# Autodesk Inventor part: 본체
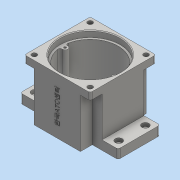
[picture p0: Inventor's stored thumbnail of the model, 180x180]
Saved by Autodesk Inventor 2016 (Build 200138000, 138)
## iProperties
Created: 2020-08
Part Number: 본체
Material: 일반
Document SubType Name: Modeling
Designer: User
Density: 1 g/cm^3
Appearance: 기본값
Mass: 324.574 g
Surface Area: 793.93 cm^2
Volume: 324.574 cm^3
Author: User
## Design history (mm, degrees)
sketch "스케치6"
  geometry: L1 (-70, 30)-(70, 30); L2 (70, 30)-(70, -30); L3 (70, -30)-(-70, -30); L4 (-70, -30)-(-70, 30); L5 (-70, 30)-(70, -30); L6 (70, 30)-(-70, -30); L7 (-33, 47)-(33, 47); L8 (33, 47)-(33, -47); L9 (33, -47)-(-33, -47); L10 (-33, -47)-(-33, 47); L11 (-33, 47)-(33, -47); L12 (33, 47)-(-33, -47); 1 further point
  constraints: 24 end point, 4 midpoint, 4 parallel, 2 horizontal, 2 perpendicular
  dimensions: "d14" = 140 distance of L2.end L3.end; "d15" = 60 distance of L1.end L2.end; "d16" = 66 distance of L8.end L9.end; "d17" = 94 distance of L7.end L8.end
extrude "돌출4" new body sketch "스케치6" distance "d18" = 13; taper "d19" = 0 deg
sketch "스케치8"
  geometry: L1 (-47, 47)-(47, 47); L2 (47, 47)-(47, -47); L3 (47, -47)-(-47, -47); L4 (-47, -47)-(-47, 47); L5 (-47, 47)-(47, -47); L6 (47, 47)-(-47, -47); 1 further point
  constraints: 12 end point, 2 midpoint, 2 parallel, 1 horizontal, 1 perpendicular
  dimensions: "d22" = 94 distance of L2.end L3.end; "d23" = 94 distance of L1.end L2.end
extrude "돌출5" join sketch "스케치8" distance "d24" = 67; taper "d25" = 0 deg
sketch "스케치10"
  geometry: L1 (33, -30)-(33, -47) reference; L2 (33, -47)-(47, -47) reference; L3 (47, -47)-(47, -30) reference; L4 (47, -30)-(33, -30) reference; L5 (-33, -47)-(-33, -30) reference; L6 (-33, -30)-(-47, -30) reference; L7 (-47, -30)-(-47, -47) reference; L8 (-47, -47)-(-33, -47) reference; L9 (-47, 47)-(47, 47) reference; L10 (33, 30)-(47, 30) reference; L11 (47, 30)-(47, 47) reference; L12 (47, 47)-(33, 47) reference; L13 (33, 47)-(33, 30) reference; L14 (-47, 30)-(-33, 30) reference; L15 (-33, 30)-(-33, 47) reference; L16 (-33, 47)-(-47, 47) reference; L17 (-47, 47)-(-47, 30) reference; 1 further point
extrude "돌출6" cut sketch "스케치10" distance "d26" = 57; taper "d27" = 0 deg
sketch "스케치11"
  geometry: C1 r 27.5 at (0, -11); 1 further point
  constraints: 1 centre point, 1 vertical alignment
  dimensions: "d28" = 55 diameter of C1; "d29" = 11 distance of point (0, 0) C1.centre
extrude "돌출7" join sketch "스케치11" distance "d30" = 7; taper "d31" = 0 deg
sketch "스케치12"
  geometry: C1 r 27.5 at (0, 0) reference; C2 r 16 at (0, 0); 1 further point
  constraints: 1 centre point, 1 coincident
  dimensions: "d32" = 32 diameter of C2
sketch "스케치13"
  geometry: C1 r 43 at (0, 0); 1 further point
  constraints: 1 centre point, 1 coincident
  dimensions: "d33" = 86 diameter of C1
extrude "돌출8" cut sketch "스케치13" distance "d34" = 9; taper "d35" = 0 deg
sketch "스케치14"
  geometry: C1 r 40 at (0, 0); 1 further point
  constraints: 1 centre point, 1 coincident
  dimensions: "d36" = 80 diameter of C1
extrude "돌출9" cut sketch "스케치14" distance "d37" = 62; taper "d38" = 0 deg
extrude "돌출10" cut sketch "스케치12" distance "d39" = 8.3; taper "d40" = 0 deg
sketch "스케치15"
  geometry: C1 r 16 at (0, -11) reference; C2 r 21 at (0, -11); C3 r 15 at (0, 20); 1 further point
  constraints: 2 centre point, 1 coincident, 1 vertical alignment
  dimensions: "d41" = 42 diameter of C2; "d42" = 30 diameter of C3; "d43" = 20 distance of C3.centre point (0, 0)
extrude "돌출11" join sketch "스케치15" distance "d45" = 7; taper "d46" = 0 deg
sketch "스케치18"
  geometry: C1 r 15 at (0, 0) reference; C2 r 21 at (0, 31) reference; C3 r 11 at (0, 0); 1 further point
  constraints: 1 centre point, 1 coincident
  dimensions: "d47" = 22 diameter of C3
extrude "돌출12" cut sketch "스케치18" distance "d48" = 7; taper "d49" = 0 deg
sketch "스케치21"
  geometry: C1 r 16 at (0, 0) reference; C2 r 12.5 at (0, 0); 1 further point
  constraints: 1 centre point, 1 coincident
  dimensions: "d51" = 25 diameter of C2
  node "투영된 루프11"
sketch "스케치22"
  geometry: C1 r 17.5 at (0, -11); A1 r 21 centre (0, -11) between (-8.978, 7.984) and (8.978, 7.984) reference; 1 further point
  constraints: 1 centre point, 1 coincident
  dimensions: "d52" = 35 diameter of C1
extrude "돌출13" cut sketch "스케치22" distance "d53" = 10; taper "d54" = 0 deg
extrude "돌출14" cut sketch "스케치21" distance "d55" = 100; taper "d56" = 0 deg
sketch "스케치23"
  geometry: C1 r 11 at (0, 0) reference; C2 r 9.5 at (0, 0); 1 further point
  constraints: 1 centre point, 1 coincident
  dimensions: "d57" = 19 diameter of C2
extrude "돌출15" cut sketch "스케치23" distance "d58" = 3; taper "d59" = 0 deg
sketch "스케치25"
  geometry: A1 r 4 centre (-36, 0) between (-36.19, -3.995) and (-36.19, 3.995); A2 r 36 centre (0, 0) between (-34.718, 9.52) and (-35.772, -4.045); A3 r 3 centre (-36.333, -6.992) between (-35.772, -4.045) and (-39.279, -7.559); A4 r 40 centre (0, 0) between (-39.279, -7.559) and (-39.279, 7.559) reference; A5 r 3 centre (-36.333, 6.992) between (-39.279, 7.559) and (-35.772, 4.045); A6 r 40 centre (0, 0) between (-39.279, 7.559) and (-39.279, -7.559); 1 further point
  constraints: 16 point on circle, 5 centre point, 4 tangent, 1 coincident, 1 horizontal alignment
  dimensions: "d60" = 8 diameter of A1; "d61" = 72 diameter of A2; "d62" = 6 diameter of A3; "d63" = 6 diameter of A5
extrude "돌출16" join sketch "스케치25" stored distance "d64" = 57; taper "d65" = 0 deg
hole "구멍1" diameter "d68" = 3.242; stored, may be unused: countersink angle "d72" = 90 deg, drill point angle "d74" = 118 deg; dims "d66" = 10, "d67" = 10, "d69" = 7, "d70" = 4, "d71" = 2, "d73" = 9
sketch "스케치26"
  geometry: C1 r 3.5 at (-40, 40); 1 further point
  constraints: 1 centre point
  dimensions: "d75" = 7 diameter of C1; "d76" = 40 horizontal distance of C1.centre point (0, 0); "d77" = 40 horizontal distance of point (0, 0) C1.centre
extrude "돌출17" cut sketch "스케치26" distance "d78" = 17.75; taper "d79" = 0 deg
sketch "스케치28"
  geometry: 2 further points
  dimensions: "d86" = 19 vertical distance of point (0, 0) point (-60, 19); "d87" = 60 horizontal distance of point (-60, 19) point (0, 0)
hole "구멍2" sketch "스케치28" at (-60, 19) diameter "d88" = 4.5; stored, may be unused: countersink angle "d92" = 90 deg, drill point angle "d94" = 118 deg; dims "d89" = 20, "d90" = 10, "d91" = 5, "d93" = 53.05
sketch "스케치29"
  geometry: L1 (-14, 80)-(80, 80) reference; L2 (66, 0)-(0, 0) reference; 3 further points
  constraints: 1 midpoint, 1 vertical alignment, 1 other
  dimensions: "d101" = 40 distance from line of L1 point (33, 40)
chamfer "모따기1" distance "d102" = 0.8; stored, may be unused: second distance "d103" = 2, angle "d104" = 30 deg
fillet "모깎기1" dims "d105" = 3
chamfer "모따기2" distance "d106" = 1; stored, may be unused: second distance "d107" = 2, angle "d108" = 30 deg
feature "엠보싱1" dims "d24" = 67, "d25" = 0, "d109" = 0.5, "d110" = 0
fillet "모깎기2" dims "d111" = 3
node "솔리드2"
mirror "대칭1"
pattern_linear "직사각형 패턴1" dims "d82" = 80
pattern_linear "직사각형 패턴2" dims "d97" = 38
node "투영된 루프5"
node "투영된 루프6"
node "투영된 루프7"
node "투영된 루프8"
node "투영된 루프12"
